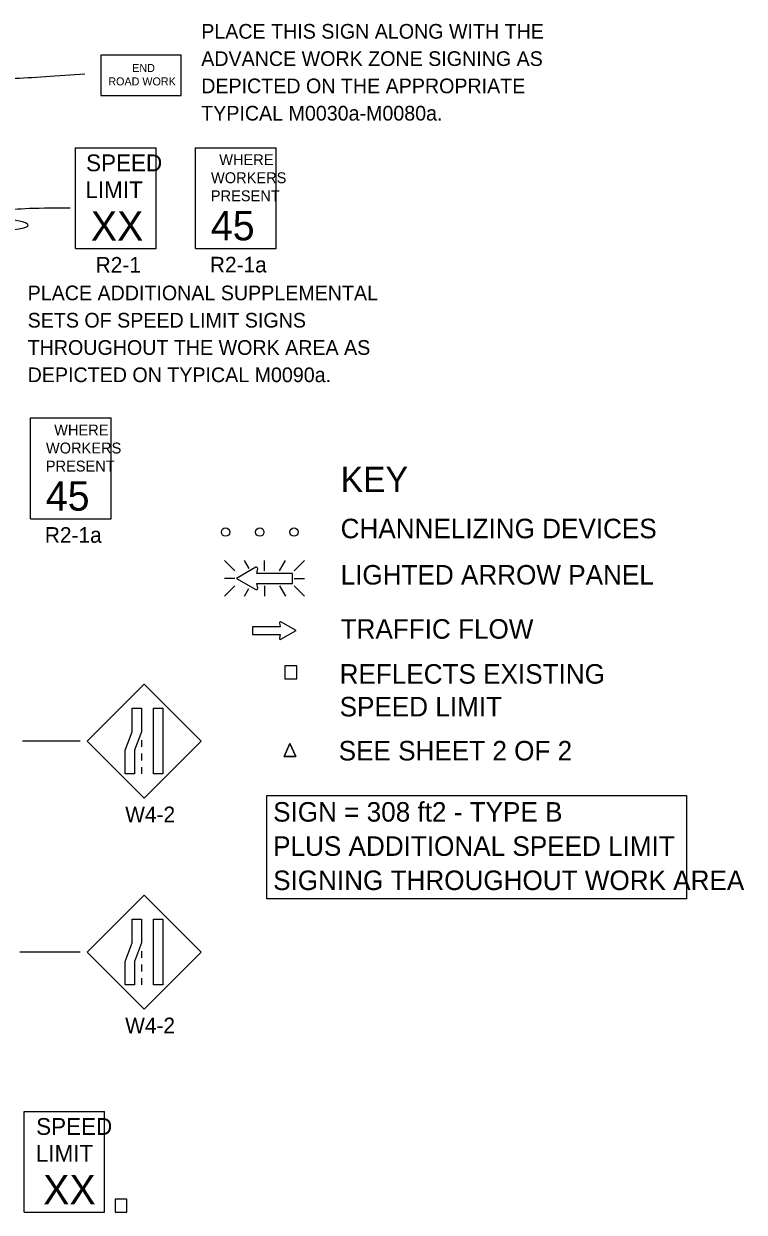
# Model space of a CAD drawing. Extents: x 16727 to 18475, y 5704 to 7011.
# Drawn here: x 17100 to 17443, y 6338 to 6905 of the extents above; entities that cross this region are included whole.
import ezdxf

# ---------------------------------------------------------------- set-up
doc = ezdxf.new("R2010")
doc.units = 0
for name, color, linetype in [('MT_SCRATCH_LEVEL_E', 7, 'Continuous'), ('TRAFFIC_SIGNS_PR', 7, 'Continuous'), ('TYPICAL_TEXT_DIMEN_EX', 7, 'Continuous'), ('TYPICAL_TEXT_DIMEN_PR', 7, 'Continuous')]:
    doc.layers.add(name, color=color, linetype=linetype)

msp = doc.modelspace()

# ---------------------------------------------------------------- linework, layer by layer
at = {"layer": 'MT_SCRATCH_LEVEL_E'}
for p, q in [((17221.93, 6619.03), (17222.24, 6617.25)), ((17221.93, 6619.03), (17222.24, 6617.25)), ((17229.85, 6615.4), (17222.61, 6619.51)), ((17229.85, 6615.4), (17222.61, 6619.51)), ((17222.24, 6617.25), (17208.99, 6617.25)), ((17208.99, 6617.25), (17208.99, 6613.51)), ((17222.24, 6617.25), (17208.99, 6617.25)), ((17208.99, 6617.25), (17208.99, 6613.51)), ((17208.99, 6613.51), (17222.24, 6613.51)), ((17208.99, 6613.51), (17222.24, 6613.51)), ((17222.24, 6613.51), (17221.93, 6611.73)), ((17222.24, 6613.51), (17221.93, 6611.73)), ((17222.61, 6611.25), (17229.85, 6615.4)), ((17222.61, 6611.25), (17229.85, 6615.4))]:
    msp.add_line(p, q, dxfattribs=at)
for centre, start, end in [((17222.39, 6619.1), 60.4248, 189.9638), ((17222.39, 6619.1), 60.4248, 189.9638), ((17222.39, 6611.66), 170.0362, 299.7731), ((17222.39, 6611.66), 170.0362, 299.7731)]:
    msp.add_arc(centre, 0.463, start, end, dxfattribs=at)
at = {"layer": 'TRAFFIC_SIGNS_PR'}
for p, q in [((17181.89, 6845.47), (17220.29, 6845.47)), ((17181.89, 6797.47), (17181.89, 6845.47)), ((17220.29, 6797.47), (17220.29, 6845.47)), ((17124.7, 6845.38), (17163.1, 6845.38)), ((17124.7, 6797.38), (17124.7, 6845.38)), ((17163.1, 6797.38), (17163.1, 6845.38)), ((17124.7, 6797.38), (17163.1, 6797.38)), ((17181.89, 6797.47), (17220.29, 6797.47)), ((17103.22, 6716.69), (17141.62, 6716.69)), ((17103.22, 6668.69), (17103.22, 6716.69)), ((17141.62, 6668.69), (17141.62, 6716.69)), ((17103.22, 6668.69), (17141.62, 6668.69)), ((17195.66, 6648.78), (17200.6, 6643.85)), ((17207.43, 6644.96), (17205.22, 6648.79)), ((17214.75, 6643.85), (17214.75, 6648.79)), ((17221.98, 6643.85), (17224.83, 6648.79)), ((17228.9, 6643.85), (17233.83, 6648.79)), ((17200.6, 6640.3), (17195.66, 6640.3)), ((17195.66, 6631.81), (17200.6, 6636.74)), ((17214.75, 6636.74), (17214.75, 6631.81)), ((17224.88, 6631.81), (17222.03, 6636.74)), ((17228.9, 6640.3), (17233.83, 6640.3)), ((17228.9, 6636.74), (17233.83, 6631.8)), ((17205.17, 6631.81), (17207.29, 6635.47)), ((17157.43, 6589.85), (17130.28, 6562.69)), ((17184.59, 6562.69), (17157.43, 6589.85)), ((17130.28, 6562.69), (17157.43, 6535.54)), ((17156.19, 6563.18), (17156.19, 6559.98)), ((17157.43, 6535.54), (17184.59, 6562.69)), ((17156.19, 6556.78), (17156.19, 6553.58)), ((17156.19, 6550.38), (17156.19, 6547.18)), ((17157.42, 6489.31), (17130.26, 6462.16)), ((17184.57, 6462.16), (17157.42, 6489.31)), ((17130.26, 6462.16), (17157.42, 6435)), ((17156.17, 6462.65), (17156.17, 6459.45)), ((17157.42, 6435), (17184.57, 6462.16)), ((17156.17, 6456.25), (17156.17, 6453.05)), ((17156.17, 6449.85), (17156.17, 6446.65)), ((17100.17, 6386.3), (17138.57, 6386.3)), ((17100.17, 6338.3), (17100.17, 6386.3)), ((17138.57, 6338.3), (17138.57, 6386.3)), ((17100.17, 6338.3), (17138.57, 6338.3))]:
    msp.add_line(p, q, dxfattribs=at)
for points in [[(17136.73, 6870.39), (17175.13, 6870.39), (17175.13, 6889.59), (17136.73, 6889.59)], [(17224.53, 6592.44), (17230.12, 6592.44), (17230.12, 6598.61), (17224.53, 6598.61)], [(17156.19, 6578.43), (17156.19, 6567.25), (17152.84, 6558.37), (17152.84, 6547.18), (17148.35, 6547.18), (17148.35, 6558.37), (17151.69, 6567.25), (17151.69, 6578.43)], [(17166.32, 6578.43), (17166.32, 6547.18), (17161.83, 6547.18), (17161.83, 6578.43)], [(17156.17, 6477.89), (17156.17, 6466.71), (17152.83, 6457.83), (17152.83, 6446.65), (17148.33, 6446.65), (17148.33, 6457.83), (17151.68, 6466.71), (17151.68, 6477.89)], [(17166.31, 6477.89), (17166.31, 6446.65), (17161.81, 6446.65), (17161.81, 6477.89)], [(17143.59, 6338.3), (17149.18, 6338.3), (17149.18, 6344.47), (17143.59, 6344.47)]]:
    msp.add_lwpolyline(points, close=True, dxfattribs=at)
for points in [[(17210.67, 6645.57), (17201.38, 6640.3), (17210.68, 6634.97)], [(17211.55, 6635.6), (17211.15, 6637.87), (17228.16, 6637.87), (17228.16, 6642.67), (17211.15, 6642.67), (17211.55, 6644.95)], [(17226.88, 6561.54), (17224.08, 6555.36)], [(17224.08, 6555.36), (17226.88, 6561.54)], [(17229.67, 6555.36), (17226.88, 6561.54)], [(17226.88, 6561.54), (17229.67, 6555.36)], [(17224.08, 6555.36), (17229.67, 6555.36)], [(17229.67, 6555.36), (17224.08, 6555.36)]]:
    msp.add_lwpolyline(points, dxfattribs=at)
for centre in [(17196.23, 6662.33), (17212.53, 6662.33), (17228.83, 6662.33)]:
    msp.add_circle(centre, 2, dxfattribs=at)
for centre, radius, start, end in [((17210.96, 6645.05), 0.598, 350.7308, 118.8916), ((17210.96, 6635.5), 0.597, 241.4833, 9.9593)]:
    msp.add_arc(centre, radius, start, end, dxfattribs=at)
msp.add_open_spline([(17129.18, 6880.47), (17013.95, 6872.23), (17127.86, 6899.81), (17029.92, 6897.64)], degree=2, dxfattribs=at)
at = {"layer": 'TYPICAL_TEXT_DIMEN_EX'}
msp.add_lwpolyline([(17215.89, 6536.8), (17415.87, 6536.8), (17415.87, 6487.6), (17215.89, 6487.6)], close=True, dxfattribs=at)
at = {"layer": 'TYPICAL_TEXT_DIMEN_PR'}
for p, q in [((17126.85, 6562.77), (17099.41, 6562.77)), ((17126.85, 6462.2), (17098.1, 6462.2))]:
    msp.add_line(p, q, dxfattribs=at)
msp.add_open_spline([(17070.66, 6805.93), (17103.88, 6805.42), (17103.88, 6811.13), (17085.32, 6811.13), (17085.32, 6815.94), (17103.5, 6816.88), (17122.14, 6816.84)], degree=3, dxfattribs=at)

# ---------------------------------------------------------------- texts
at = {"layer": 'TRAFFIC_SIGNS_PR'}
for s, height, p in [('PLACE THIS SIGN ALONG WITH THE', 7, (17184.62, 6897.4)), ('ADVANCE WORK ZONE SIGNING AS', 7, (17184.62, 6884.4)), ('END', 3.831, (17151.73, 6881.52)), ('ROAD WORK', 3.831, (17140.34, 6875.14)), ('DEPICTED ON THE APPROPRIATE', 7, (17184.62, 6871.4)), ('TYPICAL M0030a-M0080a.', 7, (17184.62, 6858.4)), ('SPEED', 8, (17129.73, 6834.24)), ('WHERE', 5.2, (17193.2, 6837.15)), ('LIMIT', 8, (17129.4, 6821.44)), ('WORKERS', 5.2, (17189.28, 6828.55)), ('PRESENT', 5.2, (17189.21, 6819.95)), ('XX', 14.031, (17132, 6801.14)), ('45', 14.031, (17189.2, 6801.32)), ('R2-1', 7.44, (17134.31, 6785.94)), ('R2-1a', 7.44, (17188.75, 6786.03)), ('PLACE ADDITIONAL SUPPLEMENTAL', 7, (17101.89, 6772.77)), ('SETS OF SPEED LIMIT SIGNS', 7, (17101.89, 6759.77)), ('THROUGHOUT THE WORK AREA AS', 7, (17101.89, 6746.77)), ('DEPICTED ON TYPICAL M0090a.', 7, (17101.89, 6733.77)), ('WHERE', 5.2, (17114.53, 6708.38)), ('WORKERS', 5.2, (17110.61, 6699.78)), ('PRESENT', 5.2, (17110.54, 6691.18)), ('45', 14.031, (17110.53, 6672.55)), ('R2-1a', 7.44, (17110.08, 6657.25)), ('W4-2', 7.44, (17148.39, 6524.1)), ('W4-2', 7.44, (17148.37, 6423.57)), ('SPEED', 8, (17105.94, 6375.16)), ('LIMIT', 8, (17105.78, 6362.36)), ('XX', 14.031, (17109.28, 6342.06))]:
    msp.add_text(s, height=height, dxfattribs=at).set_placement(p)
at = {"layer": 'TYPICAL_TEXT_DIMEN_EX'}
for s, height, p in [('KEY', 12, (17251.07, 6681.44)), ('CHANNELIZING DEVICES', 9.3, (17251.07, 6659.39)), ('LIGHTED ARROW PANEL', 9.3, (17251.07, 6637.34)), ('TRAFFIC FLOW', 9.3, (17251.07, 6611.54)), ('REFLECTS EXISTING', 9.3, (17250.58, 6590.12)), ('SPEED LIMIT', 9.3, (17250.58, 6574.52)), ('SEE SHEET 2 OF 2', 9.3, (17250.13, 6553.53)), ('SIGN = 308 ft2 - TYPE B', 9.3, (17218.9, 6524.39)), ('PLUS ADDITIONAL SPEED LIMIT', 9.3, (17218.9, 6508.09)), ('SIGNING THROUGHOUT WORK AREA', 9.3, (17218.9, 6491.79))]:
    msp.add_text(s, height=height, dxfattribs=at).set_placement(p)

doc.saveas('drawing.dxf')
